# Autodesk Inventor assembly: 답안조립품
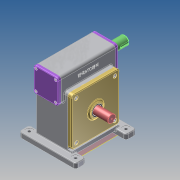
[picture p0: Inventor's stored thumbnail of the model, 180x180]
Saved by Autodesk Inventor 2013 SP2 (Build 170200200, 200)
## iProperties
Created: 2025-06
Part Number: 답안조립품
Document SubType Name: Assembly
Designer: i
Author: i
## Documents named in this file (14)
- C:\Users\i\Desktop\750603V1017\답안조립품.iam
- C:\Users\i\Desktop\750603V1017\본체.ipt
- C:\Users\i\Desktop\750603V1017\앞커버.ipt
- C:\Users\i\Desktop\750603V1017\오일 실 30 42 7.ipt
- C:\Users\i\Desktop\750603V1017\오일 실 35 55 11.ipt
- C:\Users\i\Desktop\750603V1017\웜 샤프트.ipt
- C:\Users\i\Desktop\750603V1017\웜 휠 커버.ipt
- C:\Users\i\Desktop\750603V1017\웜 휠.ipt
- C:\Users\i\Desktop\750603V1017\6각 구멍붙이 볼트 M6x12.ipt
- C:\Users\i\Desktop\750603V1017\6각 구멍붙이 볼트 M8x20.ipt
- C:\Users\i\Desktop\750603V1017\깊은 홈 볼 베어링 6206.ipt
- C:\Users\i\Desktop\750603V1017\깊은 홈 볼 베어링 6209.ipt
- C:\Users\i\Desktop\750603V1017\뒷커버.ipt
- C:\Users\i\Desktop\750603V1017\6각 구멍붙이 볼트 M6x12_MIR.ipt
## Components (12 placed, 3 different names)
1. 6각 구멍붙이 볼트 M6x12_MIR:1
2. 6각 구멍붙이 볼트 M6x12_MIR:2
3. 6각 구멍붙이 볼트 M6x12_MIR:3
4. 6각 구멍붙이 볼트 M6x12_MIR:4
5. 6각 구멍붙이 볼트 M8x20:1
6. 6각 구멍붙이 볼트 M8x20:2
7. 6각 구멍붙이 볼트 M8x20:3
8. 6각 구멍붙이 볼트 M8x20:4
9. 6각 구멍붙이 볼트 M6x12:1
10. 6각 구멍붙이 볼트 M6x12:2
11. 6각 구멍붙이 볼트 M6x12:3
12. 6각 구멍붙이 볼트 M6x12:4
